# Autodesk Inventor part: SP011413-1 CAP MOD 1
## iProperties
Created: 2007-01
Part Number: SP011413-1 CAP MOD 1
Document SubType Name: Modeling
Designer: Andy Moles
Material: ABS Plastic
Density: 1.06 g/cm^3
Mass: 2.83831 g
Surface Area: 22.7841 cm^2
Volume: 2.67765 cm^3
Author: Andy Moles
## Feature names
1. Extrusion1
2. Fillet1
3. Fillet2
4. Extrusion2
5. Extrusion3
6. Fillet3
7. Extrusion4
8. Fillet4
9. Mirror1
10. Extrusion5
